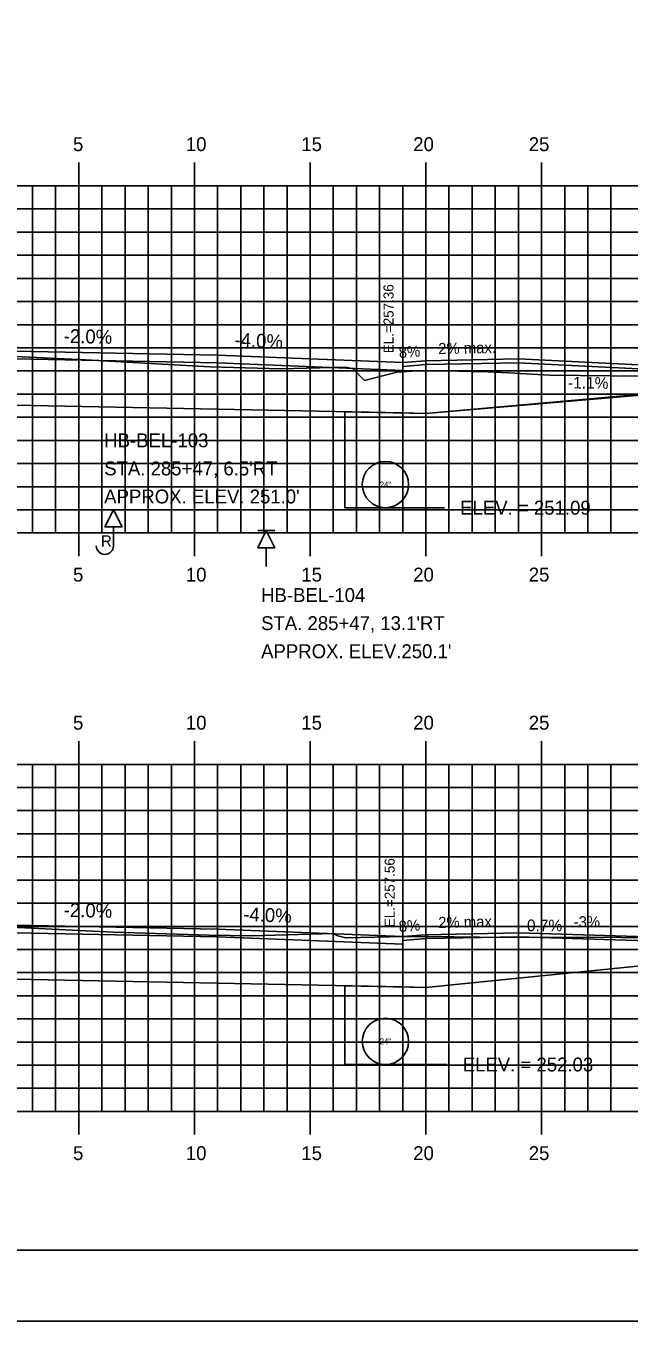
# Model space of a CAD drawing. Extents: x 856680 to 856850, y 366268 to 366378.
# Drawn here: x 856765.8 to 856791.9, y 366268.2 to 366324.1 of the extents above; entities that cross this region are included whole.
import ezdxf

# ---------------------------------------------------------------- set-up
doc = ezdxf.new("R2010")
doc.units = 0
for name, color, linetype in [('ANNOTATION', 7, 'Continuous'), ('BORDER', 7, 'Continuous'), ('D_Roadway_Drive_Gravel_RT', 7, 'Continuous'), ('D_Roadway_Drive_SubGrade', 7, 'Continuous'), ('D_Roadway_Edge_Shoulder', 7, 'Continuous'), ('D_Roadway_SubGrade', 7, 'Continuous'), ('D_Text_Monospaced', 7, 'Continuous'), ('D_Text_Standard', 7, 'Continuous'), ('H_V ANNOTATION', 7, 'Continuous'), ('JUNK COM EXC', 7, 'Continuous'), ('junk strct exc', 7, 'Continuous'), ('MAJOR', 7, 'Continuous'), ('MINOR', 7, 'Continuous'), ('PDRAIN', 7, 'Continuous'), ('PLOT BOUNDARY', 7, 'Continuous'), ('ROCKS', 7, 'Continuous'), ('S_Roadway_Centerline', 7, 'Continuous')]:
    doc.layers.add(name, color=color, linetype=linetype)

msp = doc.modelspace()

# ---------------------------------------------------------------- linework, layer by layer
at = {"layer": 'BORDER'}
msp.add_line((856688.116, 366271.236), (856848.116, 366271.236), dxfattribs=at)
at = {"layer": 'D_Roadway_Drive_Gravel_RT'}
for p, q in [((856782.116, 366309.429), (856783.13, 366309.51)), ((856782.117, 366309.596), (856783.117, 366309.676)), ((856783.117, 366309.676), (856787.117, 366309.756)), ((856783.12, 366309.509), (856787.12, 366309.589)), ((856787.108, 366309.589), (856804.736, 366308.708)), ((856787.117, 366309.756), (856804.736, 366308.875)), ((856783.117, 366284.873), (856787.117, 366284.953)), ((856787.117, 366284.953), (856795.791, 366284.69)), ((856782.116, 366284.626), (856783.13, 366284.707)), ((856782.117, 366284.793), (856783.117, 366284.873)), ((856783.12, 366284.706), (856787.12, 366284.786)), ((856787.112, 366284.786), (856795.791, 366284.523))]:
    msp.add_line(p, q, dxfattribs=at)
at = {"layer": 'D_Roadway_Drive_SubGrade'}
for p, q in [((856783.116, 366307.402), (856793.116, 366308.288)), ((856782.116, 366307.422), (856783.116, 366307.402)), ((856783.116, 366282.599), (856793.116, 366283.608)), ((856782.116, 366282.619), (856783.116, 366282.599))]:
    msp.add_line(p, q, dxfattribs=at)
at = {"layer": 'D_Roadway_Edge_Shoulder'}
for p, q in [((856782.117, 366309.596), (856782.116, 366309.262)), ((856782.117, 366284.793), (856782.116, 366284.459))]:
    msp.add_line(p, q, dxfattribs=at)
for points in [[(856744.116, 366309.596), (856752.116, 366309.916), (856763.116, 366310.136), (856774.116, 366309.916), (856782.117, 366309.596)], [(856744.116, 366284.793), (856752.116, 366285.113), (856763.116, 366285.333), (856774.116, 366285.113), (856782.117, 366284.793)]]:
    msp.add_lwpolyline(points, dxfattribs=at)
at = {"layer": 'D_Roadway_SubGrade'}
for points in [[(856752.116, 366307.582), (856752.116, 366309.582), (856763.116, 366309.802), (856774.116, 366309.582), (856774.116, 366307.582), (856763.116, 366307.802)], [(856774.116, 366309.582), (856782.116, 366309.262), (856782.116, 366307.422), (856774.116, 366307.582)], [(856752.116, 366282.779), (856752.116, 366284.779), (856763.116, 366284.999), (856774.116, 366284.779), (856774.116, 366282.779), (856763.116, 366282.999)], [(856774.116, 366284.779), (856782.116, 366284.459), (856782.116, 366282.619), (856774.116, 366282.779)]]:
    msp.add_lwpolyline(points, close=True, dxfattribs=at)
at = {"layer": 'D_Text_Standard'}
for points in [[(856783.116, 366303.326), (856783.238, 366303.326), (856783.918, 366303.326)], [(856783.116, 366279.266), (856783.346, 366279.266), (856784.026, 366279.266)]]:
    msp.add_lwpolyline(points, dxfattribs=at)
at = {"layer": 'JUNK COM EXC'}
msp.add_lwpolyline([(856783.116, 366309.234), (856783.116, 366307.402), (856783.116, 366307.402), (856793.404, 366308.273), (856804.736, 366307.707), (856804.736, 366308.874), (856804.736, 366308.874), (856804.446, 366308.878), (856788.463, 366309.06), (856786.682, 366309.152), (856785.792, 366309.195), (856784.53, 366309.232), (856783.77, 366309.239), (856783.307, 366309.238), (856783.116, 366309.234)], dxfattribs=at)
msp.add_lwpolyline([(856783.116, 366284.8), (856783.116, 366282.599), (856783.116, 366282.599), (856793.116, 366283.608), (856795.791, 366283.523), (856795.791, 366284.69), (856793.483, 366284.724), (856792.375, 366284.743), (856791.541, 366284.755), (856789.691, 366284.768), (856786.527, 366284.756), (856783.225, 366284.802)], close=True, dxfattribs=at)
at = {"layer": 'junk strct exc'}
for points in [[(856779.616, 366307.472), (856779.616, 366303.326), (856783.116, 366303.326), (856783.116, 366307.402)], [(856779.616, 366282.669), (856779.616, 366279.266), (856783.116, 366279.266), (856783.116, 366282.599)]]:
    msp.add_lwpolyline(points, close=True, dxfattribs=at)
at = {"layer": 'MAJOR'}
for p, q in [((856768.116, 366318.238), (856768.116, 366317.236)), ((856773.116, 366318.238), (856773.116, 366317.236)), ((856778.116, 366318.238), (856778.116, 366317.236)), ((856783.116, 366318.238), (856783.116, 366317.236)), ((856788.116, 366318.238), (856788.116, 366317.236)), ((856693.116, 366317.236), (856833.116, 366317.236)), ((856693.116, 366317.236), (856833.116, 366317.236)), ((856768.116, 366302.236), (856768.116, 366317.236)), ((856773.116, 366302.236), (856773.116, 366317.236)), ((856778.116, 366302.236), (856778.116, 366317.236)), ((856783.116, 366302.236), (856783.116, 366317.236)), ((856788.116, 366302.236), (856788.116, 366317.236)), ((856693.116, 366312.236), (856833.116, 366312.236)), ((856693.116, 366307.236), (856833.116, 366307.236)), ((856693.116, 366302.236), (856833.116, 366302.236)), ((856693.116, 366302.236), (856833.116, 366302.236)), ((856768.116, 366301.234), (856768.116, 366302.236)), ((856773.116, 366301.234), (856773.116, 366302.236)), ((856778.116, 366301.234), (856778.116, 366302.236)), ((856783.116, 366301.234), (856783.116, 366302.236)), ((856788.116, 366301.234), (856788.116, 366302.236)), ((856768.116, 366293.238), (856768.116, 366292.236)), ((856773.116, 366293.238), (856773.116, 366292.236)), ((856778.116, 366293.238), (856778.116, 366292.236)), ((856783.116, 366293.238), (856783.116, 366292.236)), ((856788.116, 366293.238), (856788.116, 366292.236)), ((856693.116, 366292.236), (856833.116, 366292.236)), ((856693.116, 366292.236), (856833.116, 366292.236)), ((856768.116, 366277.236), (856768.116, 366292.236)), ((856773.116, 366277.236), (856773.116, 366292.236)), ((856778.116, 366277.236), (856778.116, 366292.236)), ((856783.116, 366277.236), (856783.116, 366292.236)), ((856788.116, 366277.236), (856788.116, 366292.236)), ((856693.116, 366287.236), (856833.116, 366287.236)), ((856693.116, 366282.236), (856833.116, 366282.236)), ((856693.116, 366277.236), (856833.116, 366277.236)), ((856693.116, 366277.236), (856833.116, 366277.236)), ((856768.116, 366276.234), (856768.116, 366277.236)), ((856773.116, 366276.234), (856773.116, 366277.236)), ((856778.116, 366276.234), (856778.116, 366277.236)), ((856783.116, 366276.234), (856783.116, 366277.236)), ((856788.116, 366276.234), (856788.116, 366277.236))]:
    msp.add_line(p, q, dxfattribs=at)
at = {"layer": 'MINOR'}
for p, q in [((856766.116, 366302.236), (856766.116, 366317.236)), ((856767.116, 366302.236), (856767.116, 366317.236)), ((856769.116, 366302.236), (856769.116, 366317.236)), ((856770.116, 366302.236), (856770.116, 366317.236)), ((856771.116, 366302.236), (856771.116, 366317.236)), ((856772.116, 366302.236), (856772.116, 366317.236)), ((856774.116, 366302.236), (856774.116, 366317.236)), ((856775.116, 366302.236), (856775.116, 366317.236)), ((856776.116, 366302.236), (856776.116, 366317.236)), ((856777.116, 366302.236), (856777.116, 366317.236)), ((856779.116, 366302.236), (856779.116, 366317.236)), ((856780.116, 366302.236), (856780.116, 366317.236)), ((856781.116, 366302.236), (856781.116, 366317.236)), ((856782.116, 366302.236), (856782.116, 366317.236)), ((856784.116, 366302.236), (856784.116, 366317.236)), ((856785.116, 366302.236), (856785.116, 366317.236)), ((856786.116, 366302.236), (856786.116, 366317.236)), ((856787.116, 366302.236), (856787.116, 366317.236)), ((856789.116, 366302.236), (856789.116, 366317.236)), ((856790.116, 366302.236), (856790.116, 366317.236)), ((856791.116, 366302.236), (856791.116, 366317.236)), ((856693.116, 366316.236), (856833.116, 366316.236)), ((856693.116, 366315.236), (856833.116, 366315.236)), ((856693.116, 366314.236), (856833.116, 366314.236)), ((856693.116, 366313.236), (856833.116, 366313.236)), ((856693.116, 366311.236), (856833.116, 366311.236)), ((856693.116, 366310.236), (856833.116, 366310.236)), ((856693.116, 366309.236), (856833.116, 366309.236)), ((856693.116, 366308.236), (856833.116, 366308.236)), ((856693.116, 366306.236), (856833.116, 366306.236)), ((856693.116, 366305.236), (856833.116, 366305.236)), ((856693.116, 366304.236), (856833.116, 366304.236)), ((856693.116, 366303.236), (856833.116, 366303.236)), ((856766.116, 366277.236), (856766.116, 366292.236)), ((856767.116, 366277.236), (856767.116, 366292.236)), ((856769.116, 366277.236), (856769.116, 366292.236)), ((856770.116, 366277.236), (856770.116, 366292.236)), ((856771.116, 366277.236), (856771.116, 366292.236)), ((856772.116, 366277.236), (856772.116, 366292.236)), ((856774.116, 366277.236), (856774.116, 366292.236)), ((856775.116, 366277.236), (856775.116, 366292.236)), ((856776.116, 366277.236), (856776.116, 366292.236)), ((856777.116, 366277.236), (856777.116, 366292.236)), ((856779.116, 366277.236), (856779.116, 366292.236)), ((856780.116, 366277.236), (856780.116, 366292.236)), ((856781.116, 366277.236), (856781.116, 366292.236)), ((856782.116, 366277.236), (856782.116, 366292.236)), ((856784.116, 366277.236), (856784.116, 366292.236)), ((856785.116, 366277.236), (856785.116, 366292.236)), ((856786.116, 366277.236), (856786.116, 366292.236)), ((856787.116, 366277.236), (856787.116, 366292.236)), ((856789.116, 366277.236), (856789.116, 366292.236)), ((856790.116, 366277.236), (856790.116, 366292.236)), ((856791.116, 366277.236), (856791.116, 366292.236)), ((856693.116, 366291.236), (856833.116, 366291.236)), ((856693.116, 366290.236), (856833.116, 366290.236)), ((856693.116, 366289.236), (856833.116, 366289.236)), ((856693.116, 366288.236), (856833.116, 366288.236)), ((856693.116, 366286.236), (856833.116, 366286.236)), ((856693.116, 366285.236), (856833.116, 366285.236)), ((856693.116, 366284.236), (856833.116, 366284.236)), ((856693.116, 366283.236), (856833.116, 366283.236)), ((856693.116, 366281.236), (856833.116, 366281.236)), ((856693.116, 366280.236), (856833.116, 366280.236)), ((856693.116, 366279.236), (856833.116, 366279.236)), ((856693.116, 366278.236), (856833.116, 366278.236))]:
    msp.add_line(p, q, dxfattribs=at)
at = {"layer": 'PDRAIN'}
for points in [[(856779.616, 366307.472), (856779.616, 366303.326), (856783.116, 366303.326), (856783.116, 366307.402)], [(856779.616, 366282.669), (856779.616, 366279.266), (856783.116, 366279.266), (856783.116, 366282.599)]]:
    msp.add_lwpolyline(points, dxfattribs=at)
for centre in [(856781.366, 366304.326), (856781.366, 366280.266)]:
    msp.add_circle(centre, 1, dxfattribs=at)
at = {"layer": 'PLOT BOUNDARY'}
msp.add_lwpolyline([(856680.023, 366268.177), (856850.023, 366268.177), (856850.023, 366378.177), (856680.023, 366378.177)], close=True, dxfattribs=at)
at = {"layer": 'ROCKS'}
for p, q in [((856769.985, 366303.236), (856769.247, 366303.236)), ((856769.616, 366302.498), (856769.616, 366301.684)), ((856776.585, 366302.336), (856775.847, 366302.336)), ((856776.216, 366301.598), (856776.216, 366300.784))]:
    msp.add_line(p, q, dxfattribs=at)
for points in [[(856769.616, 366303.236), (856769.985, 366302.498), (856769.247, 366302.498)], [(856776.216, 366302.336), (856776.585, 366301.598), (856775.847, 366301.598)]]:
    msp.add_lwpolyline(points, close=True, dxfattribs=at)
msp.add_arc((856769.243, 366301.684), 0.373, 180, 0, dxfattribs=at)
at = {"layer": 'S_Roadway_Centerline'}
for points in [[(856763.242, 366309.958), (856768.411, 366309.721), (856773.773, 366309.42), (856776.841, 366309.332), (856779.652, 366309.406), (856779.978, 366309.333), (856780.458, 366308.831), (856781.867, 366309.189), (856782.491, 366309.224), (856783.307, 366309.238), (856783.77, 366309.239), (856784.53, 366309.232), (856785.792, 366309.195), (856786.682, 366309.152), (856788.463, 366309.06), (856804.446, 366308.878)], [(856726.957, 366284.253), (856740.121, 366284.928), (856741.371, 366284.942), (856743.287, 366284.909), (856744.573, 366284.919), (856744.863, 366284.759), (856745.173, 366284.642), (856749.687, 366284.775), (856752.722, 366284.944), (856758.868, 366285.156), (856763.12, 366285.297), (856769.599, 366284.982), (856773.753, 366284.86), (856775.579, 366284.829), (856779.107, 366284.922), (856779.312, 366284.832), (856779.656, 366284.734), (856781.549, 366284.779), (856783.225, 366284.802), (856786.527, 366284.756), (856789.691, 366284.768), (856791.541, 366284.755), (856792.375, 366284.743)]]:
    msp.add_lwpolyline(points, dxfattribs=at)

# ---------------------------------------------------------------- texts
at = {"layer": 'ANNOTATION'}
for s, rotation, p in [('-2.0%', 358.8542, (856767.459, 366310.449)), ('-4.0%', 357.7095, (856774.832, 366310.288)), ('-2.0%', 358.8542, (856767.459, 366285.646)), ('-4.0%', 357.7093, (856775.212, 366285.469))]:
    msp.add_text(s, height=0.6, rotation=rotation, dxfattribs=at).set_placement(p)
at = {"layer": 'D_Roadway_Drive_Gravel_RT'}
for s, rotation, p in [('8%', 4.5739, (856781.964, 366309.789)), ('2% max.', 1.1922, (856783.654, 366309.963)), ('8%', 4.5739, (856781.964, 366284.986)), ('2% max.', 1.1922, (856783.654, 366285.16))]:
    msp.add_text(s, height=0.48, rotation=rotation, dxfattribs=at).set_placement(p)
msp.add_text('-3%', height=0.48, dxfattribs=at).set_placement((856789.505, 366285.193))
at = {"layer": 'D_Text_Monospaced'}
for s, rotation, p in [('-1.1%', 359.3409, (856789.258, 366308.484)), ('-0.7%', 359.8379, (856787.261, 366285.029))]:
    msp.add_text(s, height=0.5, rotation=rotation, dxfattribs=at).set_placement(p)
at = {"layer": 'D_Text_Standard'}
for s, p in [(' EL.=257.36', (856781.72, 366309.841)), (' EL.=257.56', (856781.767, 366285.038))]:
    msp.add_text(s, height=0.4335, rotation=90, dxfattribs=at).set_placement(p)
for s, p in [('ELEV. = 251.09', (856784.598, 366303.026)), ('ELEV. = 252.03', (856784.706, 366278.966))]:
    msp.add_text(s, height=0.6, dxfattribs=at).set_placement(p)
at = {"layer": 'H_V ANNOTATION'}
for s, p in [('5', (856767.867, 366318.736)), ('10', (856772.742, 366318.736)), ('15', (856777.734, 366318.736)), ('20', (856782.57, 366318.736)), ('25', (856787.562, 366318.736)), ('5', (856767.867, 366300.136)), ('10', (856772.742, 366300.136)), ('15', (856777.734, 366300.136)), ('20', (856782.57, 366300.136)), ('25', (856787.562, 366300.136)), ('5', (856767.867, 366293.736)), ('10', (856772.742, 366293.736)), ('15', (856777.734, 366293.736)), ('20', (856782.57, 366293.736)), ('25', (856787.562, 366293.736)), ('5', (856767.867, 366275.136)), ('10', (856772.742, 366275.136)), ('15', (856777.734, 366275.136)), ('20', (856782.57, 366275.136)), ('25', (856787.562, 366275.136))]:
    msp.add_text(s, height=0.6, dxfattribs=at).set_placement(p)
at = {"layer": 'PDRAIN'}
for p in [(856781.124, 366304.201), (856781.124, 366280.141)]:
    msp.add_text('24"', height=0.25, dxfattribs=at).set_placement(p)
at = {"layer": 'ROCKS'}
for s, height, p in [('HB-BEL-103', 0.6, (856769.214, 366305.938)), ("STA. 285+47, 6.5'RT", 0.6, (856769.214, 366304.725)), ("APPROX. ELEV. 251.0'", 0.6, (856769.214, 366303.512)), ('R', 0.492, (856769.071, 366301.641)), ('HB-BEL-104', 0.6, (856775.995, 366299.252)), ("STA. 285+47, 13.1'RT", 0.6, (856775.995, 366298.038)), ("APPROX. ELEV.250.1'", 0.6, (856775.995, 366296.825))]:
    msp.add_text(s, height=height, dxfattribs=at).set_placement(p)

doc.saveas('drawing.dxf')
